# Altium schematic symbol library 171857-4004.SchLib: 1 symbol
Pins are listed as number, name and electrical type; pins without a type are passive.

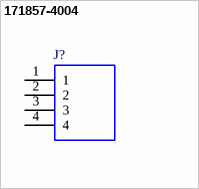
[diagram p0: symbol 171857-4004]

## 171857-4004
designator J?
Headers & Wire Housings KK RPC 254 Hdr FrLk R/A 04 Ckt 15Au T&R; Manufacturer_Name: Molex; Geometry.Height: 6.35mm
footprint HDRRA4W66P0X254_1X4_762X818X635P
pins: 1, 2, 3, 4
